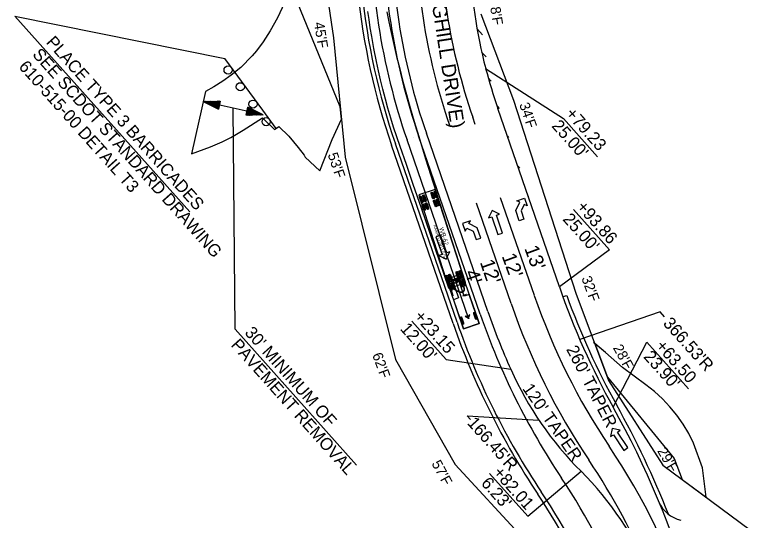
# Model space of a CAD drawing. Extents: x 1966090 to 1975830, y 788086 to 801233.
# Drawn here: x 1969167.5 to 1969532, y 798907.3 to 799154.4 of the extents above; entities that cross this region are included whole.
import ezdxf

# ---------------------------------------------------------------- set-up
doc = ezdxf.new("R2010")
doc.units = 0
for name, color, linetype in [('BR_PROPOSED_DRAINAGE', 7, 'Continuous'), ('RD_EX_Driveway_txCode', 7, 'Continuous'), ('RD_EX_GuardRail', 7, 'Continuous'), ('RD_EX_RW_TX', 7, 'Continuous'), ('RD_EX_SU_Gas', 7, 'Continuous'), ('RD_EX_Survey_Limits', 7, 'Continuous'), ('RD_PD_PaveShd', 7, 'Continuous'), ('RD_Sketch10', 7, 'Continuous'), ('RD_Sketch4', 7, 'Continuous'), ('RD_Sketch6', 7, 'Continuous'), ('RD_Sketch8', 7, 'Continuous')]:
    doc.layers.add(name, color=color, linetype=linetype)

msp = doc.modelspace()

# ---------------------------------------------------------------- linework, layer by layer
at = {"layer": 'BR_PROPOSED_DRAINAGE'}
for p, q in [((1969314.96, 799200.36), (1969323.3, 799143.16)), ((1969395.41, 799154.92), (1969411.41, 799112.72)), ((1969323.3, 799143.16), (1969329.1, 799084.76)), ((1969411.41, 799112.72), (1969441.92, 799018.26)), ((1969362.44, 799094.38), (1969362.44, 799094.38)), ((1969329.1, 799084.76), (1969353.65, 798985.94)), ((1969441.92, 799018.26), (1969457.92, 798975.61)), ((1969353.65, 798985.94), (1969382.83, 798934.48)), ((1969457.92, 798975.61), (1969484.51, 798934.16)), ((1969382.83, 798934.48), (1969418.64, 798895.74))]:
    msp.add_line(p, q, dxfattribs=at)
msp.add_lwpolyline([(1969484.51, 798934.16), (1969531.73, 798899.07), (1969532.02, 798894.68)], dxfattribs=at)
at = {"layer": 'RD_EX_Driveway_txCode'}
for p, q in [((1969412.47, 799058.73), (1969414.44, 799062.76)), ((1969412.98, 799063.48), (1969416.76, 799064.78)), ((1969414.44, 799062.76), (1969412.98, 799063.48)), ((1969416.6, 799061.71), (1969415.06, 799058.6)), ((1969418.06, 799061), (1969416.6, 799061.71)), ((1969416.76, 799064.78), (1969418.06, 799061)), ((1969414.22, 799053.68), (1969412.47, 799058.73)), ((1969415.06, 799058.6), (1969416.49, 799054.46)), ((1969416.49, 799054.46), (1969414.22, 799053.68)), ((1969390.27, 799053.75), (1969386.49, 799052.44)), ((1969386.49, 799052.44), (1969387.79, 799048.66)), ((1969389.56, 799052.29), (1969390.27, 799053.75)), ((1969393.59, 799050.33), (1969389.56, 799052.29)), ((1969387.79, 799048.66), (1969388.51, 799050.13)), ((1969388.51, 799050.13), (1969391.64, 799048.62)), ((1969391.64, 799048.62), (1969393.07, 799044.49)), ((1969395.34, 799045.27), (1969393.59, 799050.33)), ((1969393.07, 799044.49), (1969395.34, 799045.27))]:
    msp.add_line(p, q, dxfattribs=at)
for points in [[(1969403.75, 799046.93), (1969406.02, 799047.72), (1969403.03, 799056.39), (1969404.57, 799056.92), (1969400.97, 799058.67), (1969399.22, 799055.07), (1969400.76, 799055.6)], [(1969375.71, 799046.66), (1969373.44, 799045.87), (1969376.44, 799037.21), (1969374.9, 799036.67), (1969378.49, 799034.92), (1969380.24, 799038.52), (1969378.71, 799037.99)], [(1969465.33, 798941.42), (1969467.32, 798942.75), (1969462.23, 798950.38), (1969463.59, 798951.29), (1969459.66, 798952.07), (1969458.88, 798948.14), (1969460.24, 798949.05)]]:
    msp.add_lwpolyline(points, close=True, dxfattribs=at)
at = {"layer": 'RD_EX_GuardRail'}
for p, q in [((1969389.44, 799006.02), (1969359.3, 799093.3)), ((1969373.1, 799069.05), (1969365.01, 799066.42)), ((1969387.9, 799023.38), (1969373.1, 799069.05)), ((1969365.01, 799066.42), (1969379.81, 799020.76)), ((1969366.51, 799062.55), (1969365.49, 799065.69)), ((1969366.73, 799062.62), (1969365.71, 799065.76)), ((1969366.94, 799062.69), (1969365.93, 799065.83)), ((1969368.08, 799063.06), (1969367.06, 799066.2)), ((1969368.3, 799063.13), (1969367.28, 799066.27)), ((1969368.51, 799063.2), (1969367.5, 799066.34)), ((1969372.15, 799064.38), (1969371.13, 799067.52)), ((1969372.37, 799064.45), (1969371.35, 799067.59)), ((1969372.59, 799064.52), (1969371.57, 799067.66)), ((1969373.72, 799064.89), (1969372.7, 799068.02)), ((1969373.94, 799064.96), (1969372.92, 799068.1)), ((1969374.16, 799065.03), (1969373.14, 799068.17)), ((1969367.74, 799058.74), (1969366.72, 799061.88)), ((1969367.96, 799058.81), (1969366.94, 799061.95)), ((1969368.18, 799058.88), (1969367.16, 799062.02)), ((1969369.31, 799059.25), (1969368.29, 799062.39)), ((1969369.53, 799059.32), (1969368.51, 799062.46)), ((1969369.75, 799059.39), (1969368.73, 799062.53)), ((1969373.39, 799060.57), (1969372.37, 799063.71)), ((1969373.6, 799060.64), (1969372.59, 799063.78)), ((1969373.82, 799060.71), (1969372.8, 799063.85)), ((1969374.95, 799061.08), (1969373.94, 799064.22)), ((1969375.17, 799061.15), (1969374.16, 799064.29)), ((1969375.39, 799061.22), (1969374.37, 799064.36)), ((1969384.57, 799025.25), (1969383.37, 799028.71)), ((1969384.79, 799025.32), (1969383.59, 799028.79)), ((1969385, 799025.4), (1969383.81, 799028.86)), ((1969386.13, 799025.78), (1969384.93, 799029.25)), ((1969386.35, 799025.86), (1969385.15, 799029.33)), ((1969386.56, 799025.93), (1969385.37, 799029.4)), ((1969379.43, 799023.48), (1969378.24, 799026.94)), ((1969379.65, 799023.55), (1969378.45, 799027.02)), ((1969379.87, 799023.63), (1969378.67, 799027.09)), ((1969380.99, 799024.01), (1969379.8, 799027.48)), ((1969381.21, 799024.09), (1969380.01, 799027.55)), ((1969381.43, 799024.16), (1969380.23, 799027.63)), ((1969383.75, 799026.9), (1969381.04, 799025.97)), ((1969381.04, 799025.97), (1969384.5, 799015.95)), ((1969383.58, 799025.48), (1969382.06, 799024.95)), ((1969387.21, 799016.88), (1969383.75, 799026.9)), ((1969387.5, 799021.81), (1969386.3, 799025.28)), ((1969387.71, 799021.89), (1969386.52, 799025.35)), ((1969387.93, 799021.96), (1969386.74, 799025.43)), ((1969380.8, 799019.5), (1969379.61, 799022.97)), ((1969379.81, 799020.76), (1969387.9, 799023.38)), ((1969381.02, 799019.58), (1969379.82, 799023.05)), ((1969381.23, 799019.65), (1969380.04, 799023.12)), ((1969382.36, 799020.04), (1969381.17, 799023.51)), ((1969382.58, 799020.12), (1969381.38, 799023.58)), ((1969382.79, 799020.19), (1969381.6, 799023.66)), ((1969385.94, 799021.28), (1969384.74, 799024.74)), ((1969386.15, 799021.35), (1969384.96, 799024.82)), ((1969386.37, 799021.43), (1969385.18, 799024.89)), ((1969387.9, 799023.38), (1969387.9, 799023.38)), ((1969389.64, 799017.72), (1969387.21, 799016.88)), ((1969394.52, 799003.54), (1969389.64, 799017.72)), ((1969384.5, 799015.95), (1969382.07, 799015.11)), ((1969382.07, 799015.11), (1969386.96, 799000.93)), ((1969393.17, 799005.36), (1969391.97, 799008.83)), ((1969393.39, 799005.44), (1969392.19, 799008.9)), ((1969393.6, 799005.51), (1969392.41, 799008.98)), ((1969386.47, 799003.05), (1969385.28, 799006.52)), ((1969386.69, 799003.13), (1969385.49, 799006.6)), ((1969386.91, 799003.2), (1969385.71, 799006.67)), ((1969386.96, 799000.93), (1969394.52, 799003.54)), ((1969394.52, 799003.54), (1969394.52, 799003.54))]:
    msp.add_line(p, q, dxfattribs=at)
for points in [[(1969349.37, 799155.86), (1969350.37, 799150.98), (1969351.49, 799145.79), (1969352.82, 799139.95), (1969354.2, 799134.12), (1969355.73, 799127.97), (1969357.33, 799121.84), (1969359.08, 799115.4), (1969360.88, 799108.97), (1969362.83, 799102.24), (1969365.02, 799094.87), (1969368.35, 799084.01), (1969372.08, 799072.23), (1969387.82, 799023.63), (1969387.73, 799023.24), (1969393.71, 799005.9), (1969394.52, 799003.54), (1969386.96, 799000.93), (1969380.17, 799020.58), (1969379.8, 799020.8), (1969366.33, 799059.82), (1969362.35, 799071.47), (1969359.06, 799081.25), (1969355.93, 799090.02), (1969354.31, 799094.74), (1969352.76, 799099.48), (1969351.39, 799103.92), (1969349.98, 799108.71), (1969348.73, 799113.2), (1969347.46, 799118.03), (1969346.34, 799122.55), (1969345.29, 799127.1), (1969344.31, 799131.66), (1969343.07, 799137.88), (1969342.01, 799143.8), (1969341.32, 799148.09), (1969340.72, 799152.06), (1969340.18, 799156.05)], [(1969389.44, 799006.02), (1969390.07, 799007.91), (1969389.11, 799006.96), (1969387.77, 799007.12), (1969389.44, 799006.02)]]:
    msp.add_lwpolyline(points, dxfattribs=at)
for points in [[(1969367, 799062.71), (1969366.45, 799062.53), (1969366.15, 799062.92), (1969365.41, 799065.18), (1969365.44, 799065.67), (1969365.98, 799065.85), (1969366.29, 799065.46), (1969367.02, 799063.2)], [(1969368.57, 799063.21), (1969368.02, 799063.04), (1969367.72, 799063.42), (1969366.98, 799065.69), (1969367.01, 799066.18), (1969367.55, 799066.35), (1969367.86, 799065.97), (1969368.59, 799063.71)], [(1969372.64, 799064.54), (1969372.1, 799064.36), (1969371.79, 799064.75), (1969371.06, 799067.01), (1969371.08, 799067.5), (1969371.62, 799067.68), (1969371.93, 799067.29), (1969372.66, 799065.03)], [(1969374.21, 799065.04), (1969373.67, 799064.87), (1969373.36, 799065.25), (1969372.63, 799067.51), (1969372.65, 799068.01), (1969373.19, 799068.18), (1969373.5, 799067.8), (1969374.23, 799065.54)], [(1969368.23, 799058.9), (1969367.69, 799058.72), (1969367.38, 799059.11), (1969366.65, 799061.37), (1969366.67, 799061.86), (1969367.21, 799062.04), (1969367.52, 799061.65), (1969368.25, 799059.39)], [(1969369.8, 799059.41), (1969369.26, 799059.23), (1969368.95, 799059.62), (1969368.22, 799061.88), (1969368.24, 799062.37), (1969368.78, 799062.55), (1969369.09, 799062.16), (1969369.82, 799059.9)], [(1969373.88, 799060.73), (1969373.33, 799060.55), (1969373.02, 799060.94), (1969372.29, 799063.2), (1969372.31, 799063.69), (1969372.86, 799063.87), (1969373.16, 799063.48), (1969373.9, 799061.22)], [(1969375.44, 799061.24), (1969374.9, 799061.06), (1969374.59, 799061.45), (1969373.86, 799063.71), (1969373.88, 799064.2), (1969374.43, 799064.38), (1969374.73, 799063.99), (1969375.47, 799061.73)], [(1969385.06, 799025.41), (1969384.51, 799025.23), (1969384.18, 799025.66), (1969383.32, 799028.15), (1969383.32, 799028.69), (1969383.86, 799028.88), (1969384.19, 799028.45), (1969385.05, 799025.96)], [(1969386.62, 799025.95), (1969386.07, 799025.77), (1969385.74, 799026.19), (1969384.88, 799028.69), (1969384.88, 799029.23), (1969385.42, 799029.42), (1969385.75, 799028.99), (1969386.61, 799026.49)], [(1969379.92, 799023.64), (1969379.38, 799023.46), (1969379.05, 799023.89), (1969378.19, 799026.38), (1969378.18, 799026.92), (1969378.72, 799027.11), (1969379.05, 799026.68), (1969379.91, 799024.19)], [(1969381.48, 799024.18), (1969380.94, 799023.99), (1969380.61, 799024.42), (1969379.75, 799026.92), (1969379.74, 799027.46), (1969380.28, 799027.65), (1969380.61, 799027.22), (1969381.47, 799024.72)], [(1969387.98, 799021.98), (1969387.44, 799021.79), (1969387.11, 799022.22), (1969386.25, 799024.72), (1969386.25, 799025.26), (1969386.79, 799025.45), (1969387.12, 799025.02), (1969387.98, 799022.52)], [(1969381.29, 799019.67), (1969380.75, 799019.49), (1969380.42, 799019.92), (1969379.56, 799022.41), (1969379.55, 799022.95), (1969380.09, 799023.14), (1969380.42, 799022.71), (1969381.28, 799020.21)], [(1969382.85, 799020.21), (1969382.31, 799020.02), (1969381.98, 799020.45), (1969381.12, 799022.95), (1969381.11, 799023.49), (1969381.65, 799023.68), (1969381.98, 799023.25), (1969382.84, 799020.75)], [(1969386.42, 799021.44), (1969385.88, 799021.26), (1969385.55, 799021.69), (1969384.69, 799024.18), (1969384.69, 799024.72), (1969385.23, 799024.91), (1969385.56, 799024.48), (1969386.42, 799021.99)], [(1969389.44, 799006.02), (1969390.07, 799007.91), (1969389.11, 799006.96), (1969387.77, 799007.12)], [(1969393.66, 799005.53), (1969393.12, 799005.35), (1969392.78, 799005.77), (1969391.92, 799008.27), (1969391.92, 799008.81), (1969392.46, 799009), (1969392.79, 799008.57), (1969393.65, 799006.07)], [(1969386.96, 799003.22), (1969386.42, 799003.04), (1969386.09, 799003.47), (1969385.23, 799005.96), (1969385.22, 799006.5), (1969385.76, 799006.69), (1969386.09, 799006.26), (1969386.95, 799003.76)]]:
    msp.add_lwpolyline(points, close=True, dxfattribs=at)
for centre, radius in [((1969359.3, 799093.3), 0.0417), ((1969383.08, 799024.45), 0.34), ((1969389.44, 799006.02), 0.0417)]:
    msp.add_circle(centre, radius, dxfattribs=at)
for centre, radius, start, end in [((1969665.13, 799198.91), 323.56, 178.558, 199.0518), ((1969383.08, 799024.45), 1.14, 154.0202, 64.0202)]:
    msp.add_arc(centre, radius, start, end, dxfattribs=at)
at = {"layer": 'RD_EX_SU_Gas'}
for p, q in [((1969288.76, 799107.74), (1969270.16, 799133.03)), ((1969295.27, 799098.9), (1969288.76, 799107.74)), ((1969392.66, 799100.84), (1969391.43, 799104.4)), ((1969410.23, 799013.2), (1969393.29, 799062.27)), ((1969421.58, 799017.12), (1969405.09, 799064.87))]:
    msp.add_line(p, q, dxfattribs=at)
for centre in [(1969271.77, 799127.43), (1969277.75, 799119.24), (1969283.94, 799110.76), (1969290.37, 799102.15)]:
    msp.add_circle(centre, 2, dxfattribs=at)
for centre, radius, start, end in [((1969665.13, 799198.91), 301.56, 178.558, 199.0518), ((1969665.13, 799198.91), 289.56, 178.558, 199.0518), ((1969724.99, 799121.9), 321, 199.0518, 213.7837), ((1969724.99, 799121.9), 333, 199.0518, 213.7837), ((1969171.45, 798751.56), 345, 3.6771, 33.7837), ((1969171.45, 798751.56), 333, 22.8293, 33.7837)]:
    msp.add_arc(centre, radius, start, end, dxfattribs=at)
at = {"layer": 'RD_EX_Survey_Limits'}
for p, q in [((1969395.11, 799007.98), (1969364.97, 799095.26)), ((1969398.89, 799009.28), (1969368.75, 799096.56))]:
    msp.add_line(p, q, dxfattribs=at)
for centre, radius, start, end in [((1969665.13, 799198.91), 317.56, 178.558, 199.0518), ((1969665.13, 799198.91), 313.56, 178.558, 199.0518), ((1969724.99, 799121.9), 349, 199.0518, 213.7837), ((1969724.99, 799121.9), 345, 199.0518, 204.0911), ((1969561.99, 799049.01), 166.45, 204.0911, 225.0596), ((1969333.04, 798819.58), 157.68, 22.8293, 45.0596), ((1969171.45, 798751.56), 317, 9.1587, 33.7837)]:
    msp.add_arc(centre, radius, start, end, dxfattribs=at)
at = {"layer": 'RD_PD_PaveShd'}
for p, q in [((1969381.88, 799003.41), (1969351.74, 799090.69)), ((1969435.66, 799016.6), (1969437.41, 799017.23))]:
    msp.add_line(p, q, dxfattribs=at)
for centre, radius, start, end in [((1969665.13, 799198.91), 331.56, 185.7857, 199.0518), ((1969780.29, 799140.99), 364.53, 199.8469, 209.1352), ((1969724.99, 799121.9), 363, 199.0518, 213.7837), ((1969069.93, 798745.04), 448.74, 21.5926, 29.1352), ((1969171.45, 798751.56), 303, 9.1587, 33.7837)]:
    msp.add_arc(centre, radius, start, end, dxfattribs=at)
at = {"layer": 'RD_Sketch10'}
for p, q in [((1969456.32, 798989.24), (1969451.14, 798993.7)), ((1969451.14, 798993.7), (1969457.3, 798977.26)), ((1969457.3, 798977.26), (1969490.04, 798937.38)), ((1969490.04, 798937.38), (1969493.83, 798927.23)), ((1969493.83, 798927.23), (1969493.83, 798927.23))]:
    msp.add_line(p, q, dxfattribs=at)
for points in [[(1969309.4, 799084.74), (1969316.6, 799078.12), (1969322.6, 799093.43), (1969327.26, 799103.33), (1969326.65, 799109.43), (1969302.8, 799167.77), (1969295.98, 799152.92), (1969292.43, 799146.6), (1969288.89, 799141.21), (1969285.66, 799136.83), (1969283.61, 799134.3), (1969278.08, 799128.66), (1969273.33, 799124.84), (1969269.12, 799121.91), (1969264.78, 799119.21), (1969260.7, 799116.89), (1969253.89, 799086.39), (1969263.16, 799089.89), (1969268.86, 799092.37), (1969273.07, 799094.47), (1969275.13, 799095.61), (1969279.14, 799098.07), (1969288.58, 799104.1), (1969289.04, 799103.48), (1969294.55, 799098.41)], [(1969294.55, 799098.41), (1969296.57, 799099.77), (1969301.49, 799095), (1969306.09, 799089.55), (1969308.96, 799085.74), (1969309.4, 799084.74)], [(1969456.32, 798989.24), (1969450.54, 798994.21)], [(1969493.83, 798927.23), (1969505.6, 798918.49), (1969503.88, 798932.85), (1969499.47, 798944.96), (1969497.09, 798949.72), (1969494.36, 798954.28), (1969491.3, 798958.63), (1969487.93, 798962.74), (1969484.26, 798966.59), (1969480.31, 798970.15), (1969476.12, 798973.41), (1969464.76, 798981.98), (1969456.32, 798989.24)]]:
    msp.add_lwpolyline(points, dxfattribs=at)
at = {"layer": 'RD_Sketch4'}
msp.add_arc((1969496.41, 798921.99), 15, 202.5345, 257.8806, dxfattribs=at)
at = {"layer": 'RD_Sketch6'}
for p, q in [((1969167.48, 799153.83), (1969270.16, 799133.03)), ((1969167.48, 799153.83), (1969253.05, 799058)), ((1969397.77, 799128.19), (1969435.79, 799103.75)), ((1969259.59, 799112.02), (1969267.94, 799112.23)), ((1969267.5, 799110.25), (1969259.59, 799112.02)), ((1969259.59, 799112.02), (1969267.06, 799108.28)), ((1969288.89, 799105.48), (1969259.59, 799112.02)), ((1969267.94, 799112.23), (1969267.06, 799108.28)), ((1969280.55, 799105.27), (1969281.43, 799109.22)), ((1969288.89, 799105.48), (1969281.43, 799109.22)), ((1969275.17, 799000.65), (1969274.24, 799108.75)), ((1969288.89, 799105.48), (1969280.55, 799105.27)), ((1969280.99, 799107.24), (1969288.89, 799105.48)), ((1969433.86, 799021.36), (1969403.72, 799108.64)), ((1969452.55, 799084.98), (1969435.79, 799103.75)), ((1969458.3, 799039.57), (1969440.73, 799059.25)), ((1969378.44, 798985.8), (1969361.68, 799004.57)), ((1969334.54, 798934.15), (1969275.17, 799000.65)), ((1969378.44, 798985.8), (1969410.04, 798981.07))]:
    msp.add_line(p, q, dxfattribs=at)
for points in [[(1969267.41, 799110.33), (1969260.05, 799111.98), (1969267.47, 799110.37), (1969260.41, 799111.96), (1969267.46, 799110.46), (1969260.65, 799111.98), (1969267.46, 799110.56), (1969260.95, 799112), (1969267.5, 799110.64), (1969261.4, 799112), (1969267.54, 799110.75), (1969261.88, 799112), (1969267.53, 799110.86), (1969262.24, 799112), (1969267.56, 799110.93), (1969262.65, 799112.01), (1969267.53, 799111.03), (1969263.01, 799112.02), (1969267.62, 799111.09), (1969263.33, 799112.03), (1969267.61, 799111.22), (1969263.78, 799112.05), (1969267.65, 799111.31), (1969264.32, 799112.04), (1969267.68, 799111.4), (1969264.7, 799112.09), (1969267.71, 799111.5), (1969265.26, 799112.1), (1969267.7, 799111.61), (1969265.72, 799112.08), (1969267.77, 799111.71), (1969266.12, 799112.1), (1969267.76, 799111.8), (1969266.49, 799112.12), (1969267.83, 799111.89), (1969266.93, 799112.12), (1969267.78, 799111.98), (1969267.43, 799112.13), (1969267.77, 799112.09)], [(1969260.09, 799111.85), (1969267.39, 799110.22), (1969260.34, 799111.74), (1969267.36, 799110.12), (1969260.58, 799111.64), (1969267.38, 799110.05), (1969260.79, 799111.5), (1969267.35, 799109.99), (1969261.05, 799111.36), (1969267.35, 799109.9), (1969261.29, 799111.23), (1969267.33, 799109.83), (1969261.59, 799111.08), (1969267.33, 799109.75), (1969261.94, 799110.92), (1969267.29, 799109.64), (1969262.26, 799110.78), (1969267.31, 799109.57), (1969262.58, 799110.62), (1969267.27, 799109.49), (1969262.89, 799110.45), (1969267.26, 799109.41), (1969263.23, 799110.29), (1969267.19, 799109.35), (1969263.68, 799110.07), (1969267.21, 799109.26), (1969263.97, 799109.9), (1969267.22, 799109.19), (1969264.35, 799109.69), (1969267.17, 799109.12), (1969264.74, 799109.54), (1969267.14, 799109.02), (1969265.05, 799109.38), (1969267.06, 799108.93), (1969265.34, 799109.2), (1969267.05, 799108.87), (1969265.79, 799109.01), (1969267.09, 799108.74), (1969266.06, 799108.88), (1969267.06, 799108.61), (1969266.23, 799108.74), (1969266.95, 799108.5), (1969267.01, 799108.4), (1969266.96, 799108.53)], [(1969288.39, 799105.65), (1969281.1, 799107.28), (1969288.14, 799105.76), (1969281.12, 799107.38), (1969287.91, 799105.86), (1969281.1, 799107.45), (1969287.7, 799105.99), (1969281.13, 799107.51), (1969287.44, 799106.14), (1969281.13, 799107.6), (1969287.19, 799106.26), (1969281.15, 799107.66), (1969286.9, 799106.41), (1969281.15, 799107.75), (1969286.54, 799106.58), (1969281.19, 799107.86), (1969286.23, 799106.72), (1969281.17, 799107.93), (1969285.9, 799106.87), (1969281.21, 799108.01), (1969285.6, 799107.05), (1969281.23, 799108.09), (1969285.25, 799107.21), (1969281.29, 799108.14), (1969284.81, 799107.43), (1969281.28, 799108.23), (1969284.52, 799107.6), (1969281.26, 799108.31), (1969284.13, 799107.8), (1969281.31, 799108.38), (1969283.74, 799107.96), (1969281.35, 799108.48), (1969283.43, 799108.11), (1969281.42, 799108.56), (1969283.14, 799108.3), (1969281.43, 799108.63), (1969282.69, 799108.48), (1969281.39, 799108.76), (1969282.43, 799108.61), (1969281.42, 799108.89), (1969282.25, 799108.75), (1969281.53, 799109), (1969281.47, 799109.1), (1969281.53, 799108.97)], [(1969281.07, 799107.16), (1969288.43, 799105.52), (1969281.01, 799107.12), (1969288.07, 799105.53), (1969281.03, 799107.04), (1969287.83, 799105.52), (1969281.02, 799106.93), (1969287.53, 799105.5), (1969280.99, 799106.86), (1969287.09, 799105.49), (1969280.94, 799106.75), (1969286.61, 799105.5), (1969280.95, 799106.64), (1969286.25, 799105.49), (1969280.92, 799106.56), (1969285.83, 799105.48), (1969280.95, 799106.47), (1969285.47, 799105.48), (1969280.87, 799106.4), (1969285.16, 799105.46), (1969280.87, 799106.28), (1969284.71, 799105.44), (1969280.84, 799106.19), (1969284.16, 799105.46), (1969280.8, 799106.09), (1969283.79, 799105.41), (1969280.78, 799105.99), (1969283.22, 799105.4), (1969280.79, 799105.89), (1969282.76, 799105.41), (1969280.71, 799105.78), (1969282.36, 799105.4), (1969280.73, 799105.69), (1969282, 799105.38), (1969280.66, 799105.61), (1969281.55, 799105.37), (1969280.7, 799105.51), (1969281.05, 799105.37), (1969280.71, 799105.41)], [(1969458.3, 799039.57), (1969458.3, 799039.57), (1969433.86, 799021.36)], [(1969485.27, 799006.69), (1969483.11, 799009.12), (1969443.87, 798995.57)], [(1969460.14, 798962.54), (1969476.58, 798994.31), (1969496.96, 798971.46)], [(1969390.33, 798956.57), (1969388.79, 798958.3), (1969423.83, 798956.19)], [(1969399.72, 798930.18), (1969418.32, 798909.32), (1969444.42, 798931.2)]]:
    msp.add_lwpolyline(points, dxfattribs=at)
at = {"layer": 'RD_Sketch8'}
for p, q in [((1969393.51, 799147.78), (1969396.28, 799144.68)), ((1969395.81, 799136.2), (1969397.96, 799133.8)), ((1969399.03, 799123.58), (1969400.46, 799121.98)), ((1969403.34, 799109.75), (1969404.33, 799108.64)), ((1969433.84, 799021.35), (1969403.72, 799108.64)), ((1969408.41, 799095.07), (1969409, 799094.4)), ((1969383.77, 799004.06), (1969353.63, 799091.34)), ((1969413.47, 799080.39), (1969414.29, 799079.47)), ((1969418.54, 799065.7), (1969418.67, 799065.55))]:
    msp.add_line(p, q, dxfattribs=at)
for centre, radius, start, end in [((1969615.29, 799185.73), 225, 181.1011, 194.816), ((1969665.13, 799198.91), 329.56, 185.7857, 199.0518), ((1969665.13, 799198.91), 276.56, 194.816, 199.0518), ((1969780.29, 799140.99), 366.53, 199.0518, 209.1352), ((1969724.99, 799121.9), 361, 199.0518, 213.7837), ((1969069.93, 798745.04), 446.74, 3.6771, 29.1352), ((1969171.45, 798751.56), 305, 9.1587, 33.7837)]:
    msp.add_arc(centre, radius, start, end, dxfattribs=at)

# ---------------------------------------------------------------- texts
at = {"layer": 'RD_EX_Driveway_txCode'}
for s, rotation, p in [('(MORNINGHILL DRIVE)', 278.6775, (1969365.29, 799199.87)), ("13'", 290.1655, (1969416.59, 799040.27)), ("12'", 290.1655, (1969405.53, 799036.45)), ("12'", 289.0518, (1969394.85, 799033.5)), ("4'", 289.0518, (1969387.4, 799028.52)), ("12'", 288.0951, (1969378.38, 799026.22))]:
    msp.add_text(s, height=7, rotation=rotation, dxfattribs=at).set_placement(p)
at = {"layer": 'RD_EX_GuardRail'}
for s, height, p in [('AASHTO 2011 (US)', 1.4167, (1969372.09, 799051.44)), ('WB-62', 2.125, (1969374.98, 799050.01)), ('(c) 2021 Transoft Solutions, Inc. All rights reserved.', 0.085, (1969375.88, 799046.54))]:
    msp.add_text(s, height=height, rotation=287.9615, dxfattribs=at).set_placement(p)
at = {"layer": 'RD_EX_RW_TX'}
for s, rotation, p in [("28'F", 279.263, (1969399.37, 799161.68)), ("45'F", 279.263, (1969313.78, 799150.46)), ("34'F", 288.763, (1969414.13, 799110.61)), ("53'F", 288.763, (1969320.42, 799086.11)), ("32'F", 290.1084, (1969444.54, 799025.64)), ("28'F", 298.7114, (1969459.89, 798991.62)), ("62'F", 290.1084, (1969342.19, 798988.17)), ("29'F", 300.2531, (1969481.55, 798941.15)), ("57'F", 298.7114, (1969371.16, 798934.96))]:
    msp.add_text(s, height=5, rotation=rotation, dxfattribs=at).set_placement(p)
at = {"layer": 'RD_Sketch6'}
for s, height, rotation, p in [('PLACE TYPE 3 BARRICADES', 5.9996, 311.7871, (1969182.43, 799140.79)), ('SEE SCDOT STANDARD DRAWING', 5.9996, 311.7871, (1969175.72, 799134.8)), ('610-515-00 DETAIL T3', 5.9996, 311.7871, (1969169.01, 799128.8)), ('+79.23', 6, 311.7606, (1969436.46, 799105.85)), ("25.00'", 6, 311.7606, (1969429.75, 799099.86)), ('+93.86', 6, 311.7606, (1969441.85, 799060.25)), ("25.00'", 6, 311.7606, (1969435.13, 799054.25)), ('+23.15', 6, 311.7606, (1969362.35, 799006.67)), ("12.00'", 6, 311.7606, (1969355.63, 799000.67)), ("366.53'R", 6, 311.7255, (1969484.21, 799003.3)), ("30' MINIMUM OF", 5.9996, 311.7871, (1969279.55, 798998.74)), ('PAVEMENT REMOVAL', 5.9996, 311.7871, (1969272.84, 798992.74)), ("260' TAPER", 6, 297.1961, (1969437.05, 798990.9)), ('+63.50', 6, 311.7255, (1969480.55, 798992.23)), ("23.90'", 6, 311.7255, (1969474.68, 798987)), ("120' TAPER", 6, 304.686, (1969415.52, 798971.6)), ("166.45'R", 6, 311.7255, (1969388.42, 798954.59)), ('+82.01', 6, 311.7255, (1969401.05, 798930.35)), ("6.23'", 6, 311.7255, (1969395.18, 798925.12))]:
    msp.add_text(s, height=height, rotation=rotation, dxfattribs=at).set_placement(p)

doc.saveas('drawing.dxf')
